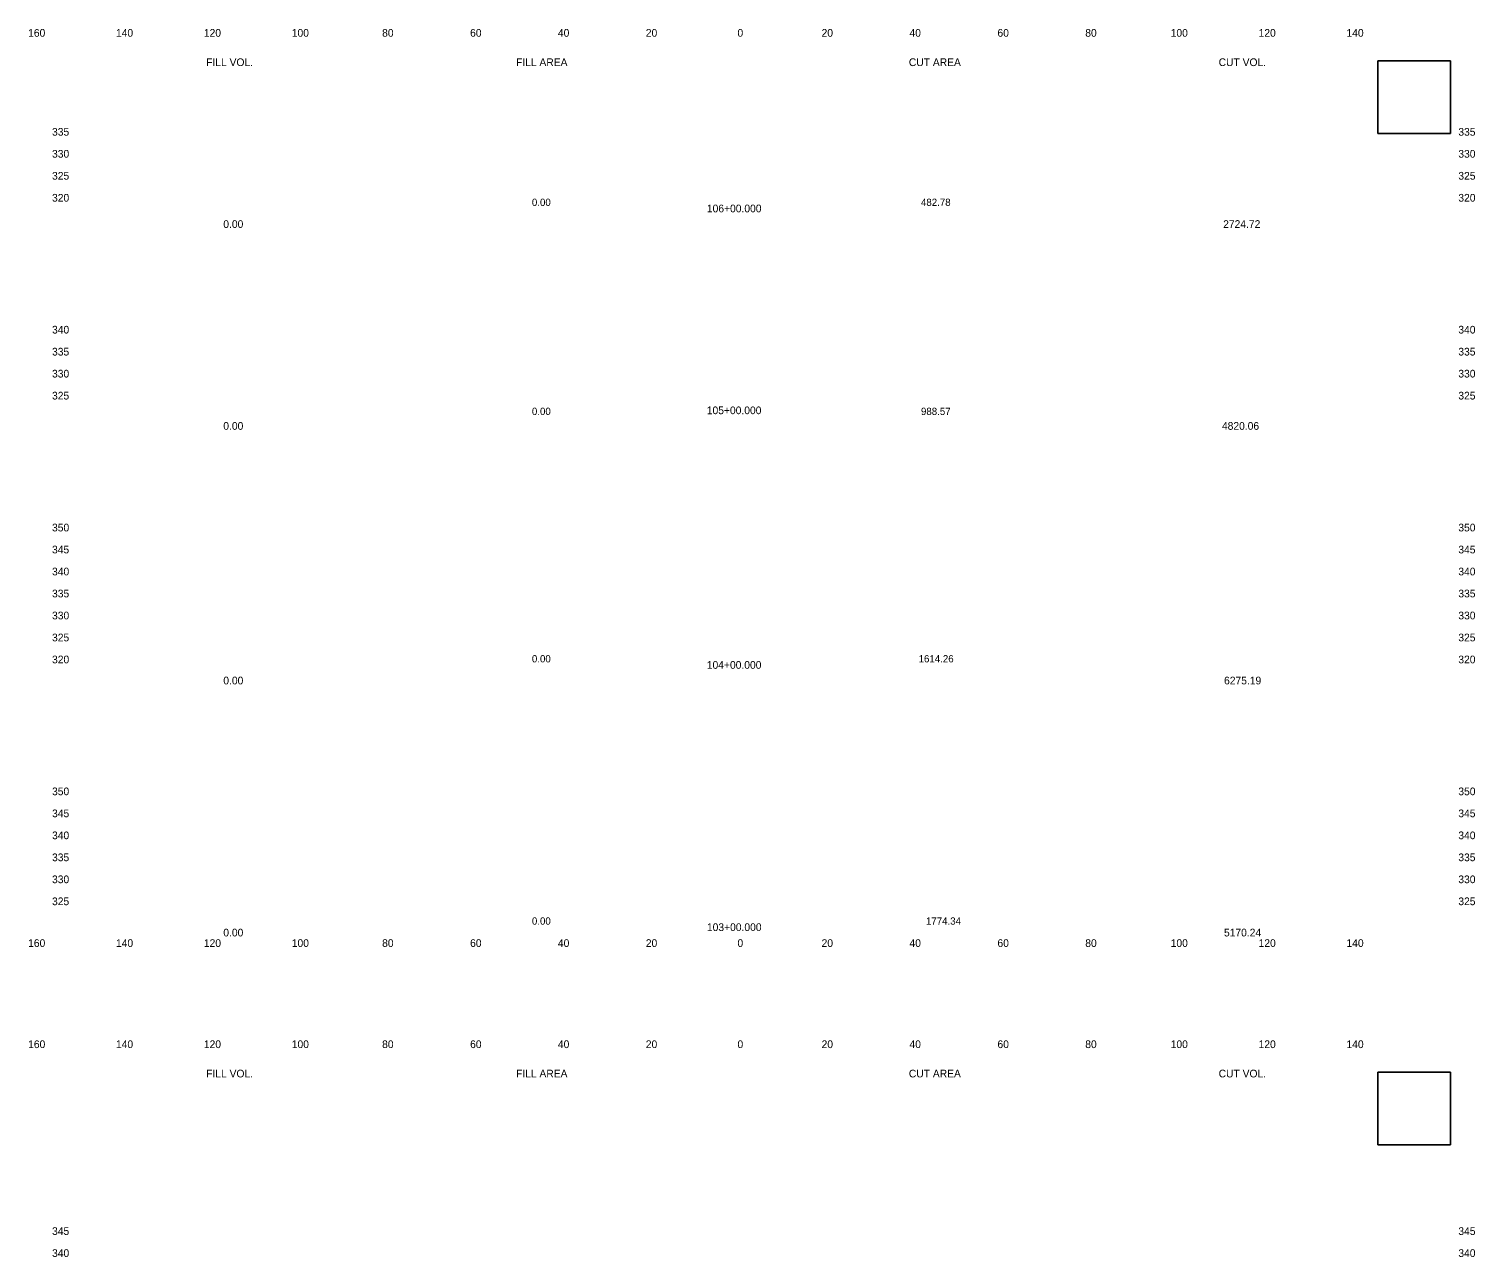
# Model space of a CAD drawing. Extents: x 21477 to 21806, y 6470 to 11049.
# Drawn here: x 21477.1 to 21806.1, y 7319.8 to 7599.1 of the extents above; entities that cross this region are included whole.
import ezdxf

# ---------------------------------------------------------------- set-up
doc = ezdxf.new("R2010")
doc.units = 0
for name, color, linetype in [('SHEET_CONSULTANT_STAMP', 7, 'Continuous'), ('XS_SHEET_EW_TX_AREA', 7, 'Continuous'), ('XS_SHEET_EW_TX_VOLUME', 7, 'Continuous'), ('XS_SHEET_LABELS_ELEVATION', 7, 'Continuous'), ('XS_SHEET_LABELS_OFFSET', 7, 'Continuous'), ('XS_SHEET_LABELS_STATION', 7, 'Continuous'), ('XS_SHEET_TX', 7, 'Continuous')]:
    doc.layers.add(name, color=color, linetype=linetype)

msp = doc.modelspace()

# ---------------------------------------------------------------- linework, layer by layer
at = {"layer": 'SHEET_CONSULTANT_STAMP'}
for points in [[(21784.04, 7575.34), (21800.54, 7575.34), (21800.54, 7591.84), (21784.04, 7591.84)], [(21784.04, 7345.34), (21800.54, 7345.34), (21800.54, 7361.84), (21784.04, 7361.84)]]:
    msp.add_lwpolyline(points, close=True, dxfattribs=at)

# ---------------------------------------------------------------- texts
at = {"layer": 'XS_SHEET_EW_TX_AREA'}
for s, p in [(' 0.00 ', (21590.92, 7558.86)), (' 482.78 ', (21679.45, 7558.86)), (' 0.00 ', (21590.92, 7511.32)), (' 988.57 ', (21679.45, 7511.32)), (' 0.00 ', (21590.92, 7455.05)), (' 1614.26 ', (21678.91, 7455.05)), (' 0.00 ', (21590.92, 7395.41)), (' 1774.34 ', (21680.58, 7395.41))]:
    msp.add_text(s, height=1.65, dxfattribs=at).set_placement(p)
at = {"layer": 'XS_SHEET_EW_TX_VOLUME'}
for s, p in [(' 0.00 ', (21520.66, 7553.86)), (' 2724.72 ', (21748.18, 7553.86)), (' 0.00 ', (21520.66, 7507.95)), (' 4820.06 ', (21747.9, 7507.95)), (' 0.00 ', (21520.66, 7450.05)), (' 6275.19 ', (21748.38, 7450.05)), (' 0.00 ', (21520.66, 7392.73)), (' 5170.24 ', (21748.36, 7392.73))]:
    msp.add_text(s, height=1.75, dxfattribs=at).set_placement(p)
at = {"layer": 'XS_SHEET_LABELS_ELEVATION'}
for s, p in [('  335  ', (21481.04, 7574.84)), ('  335  ', (21801.04, 7574.84)), ('  330  ', (21481.04, 7569.84)), ('  330  ', (21801.04, 7569.84)), ('  325  ', (21481.04, 7564.84)), ('  325  ', (21801.04, 7564.84)), ('  320  ', (21481.04, 7559.84)), ('  320  ', (21801.04, 7559.84)), ('  340  ', (21481.04, 7529.84)), ('  340  ', (21801.04, 7529.84)), ('  335  ', (21481.04, 7524.84)), ('  335  ', (21801.04, 7524.84)), ('  330  ', (21481.04, 7519.84)), ('  330  ', (21801.04, 7519.84)), ('  325  ', (21481.04, 7514.84)), ('  325  ', (21801.04, 7514.84)), ('  350  ', (21481.04, 7484.84)), ('  350  ', (21801.04, 7484.84)), ('  345  ', (21481.04, 7479.84)), ('  345  ', (21801.04, 7479.84)), ('  340  ', (21481.04, 7474.84)), ('  340  ', (21801.04, 7474.84)), ('  335  ', (21481.04, 7469.84)), ('  335  ', (21801.04, 7469.84)), ('  330  ', (21481.04, 7464.84)), ('  330  ', (21801.04, 7464.84)), ('  325  ', (21481.04, 7459.84)), ('  325  ', (21801.04, 7459.84)), ('  320  ', (21481.04, 7454.84)), ('  320  ', (21801.04, 7454.84)), ('  350  ', (21481.04, 7424.84)), ('  350  ', (21801.04, 7424.84)), ('  345  ', (21481.04, 7419.84)), ('  345  ', (21801.04, 7419.84)), ('  340  ', (21481.04, 7414.84)), ('  340  ', (21801.04, 7414.84)), ('  335  ', (21481.04, 7409.84)), ('  335  ', (21801.04, 7409.84)), ('  330  ', (21481.04, 7404.84)), ('  330  ', (21801.04, 7404.84)), ('  325  ', (21481.04, 7399.84)), ('  325  ', (21801.04, 7399.84)), ('  345  ', (21481.04, 7324.84)), ('  345  ', (21801.04, 7324.84)), ('  340  ', (21481.04, 7319.84)), ('  340  ', (21801.04, 7319.84))]:
    msp.add_text(s, height=1.75, dxfattribs=at).set_placement(p)
at = {"layer": 'XS_SHEET_LABELS_OFFSET'}
for s, p in [('  160  ', (21475.6, 7597.34)), ('  140  ', (21495.59, 7597.34)), ('  120  ', (21515.59, 7597.34)), ('  100  ', (21535.59, 7597.34)), ('  80  ', (21556.15, 7597.34)), ('  60  ', (21576.17, 7597.34)), ('  40  ', (21596.15, 7597.34)), ('  20  ', (21616.15, 7597.34)), ('  0  ', (21637.01, 7597.34)), ('  0  ', (21637.01, 7597.34)), ('  20  ', (21656.15, 7597.34)), ('  40  ', (21676.15, 7597.34)), ('  60  ', (21696.17, 7597.34)), ('  80  ', (21716.15, 7597.34)), ('  100  ', (21735.59, 7597.34)), ('  120  ', (21755.59, 7597.34)), ('  140  ', (21775.59, 7597.34)), ('  160  ', (21475.6, 7390.34)), ('  140  ', (21495.59, 7390.34)), ('  120  ', (21515.59, 7390.34)), ('  100  ', (21535.59, 7390.34)), ('  80  ', (21556.15, 7390.34)), ('  60  ', (21576.17, 7390.34)), ('  40  ', (21596.15, 7390.34)), ('  20  ', (21616.15, 7390.34)), ('  0  ', (21637.01, 7390.34)), ('  0  ', (21637.01, 7390.34)), ('  20  ', (21656.15, 7390.34)), ('  40  ', (21676.15, 7390.34)), ('  60  ', (21696.17, 7390.34)), ('  80  ', (21716.15, 7390.34)), ('  100  ', (21735.59, 7390.34)), ('  120  ', (21755.59, 7390.34)), ('  140  ', (21775.59, 7390.34)), ('  160  ', (21475.6, 7367.34)), ('  140  ', (21495.59, 7367.34)), ('  120  ', (21515.59, 7367.34)), ('  100  ', (21535.59, 7367.34)), ('  80  ', (21556.15, 7367.34)), ('  60  ', (21576.17, 7367.34)), ('  40  ', (21596.15, 7367.34)), ('  20  ', (21616.15, 7367.34)), ('  0  ', (21637.01, 7367.34)), ('  0  ', (21637.01, 7367.34)), ('  20  ', (21656.15, 7367.34)), ('  40  ', (21676.15, 7367.34)), ('  60  ', (21696.17, 7367.34)), ('  80  ', (21716.15, 7367.34)), ('  100  ', (21735.59, 7367.34)), ('  120  ', (21755.59, 7367.34)), ('  140  ', (21775.59, 7367.34))]:
    msp.add_text(s, height=1.75, dxfattribs=at).set_placement(p)
at = {"layer": 'XS_SHEET_LABELS_STATION'}
for s, p in [('  106+00.000  ', (21630.05, 7557.41)), ('  105+00.000  ', (21630.03, 7511.5)), ('  104+00.000  ', (21630.03, 7453.6)), ('  103+00.000  ', (21630.06, 7393.96))]:
    msp.add_text(s, height=1.75, dxfattribs=at).set_placement(p)
at = {"layer": 'XS_SHEET_TX'}
for s, p in [('FILL VOL.', (21517.41, 7590.67)), ('FILL AREA', (21587.92, 7590.67)), ('CUT AREA', (21677.31, 7590.67)), ('CUT VOL.', (21747.8, 7590.67)), ('FILL VOL.', (21517.41, 7360.67)), ('FILL AREA', (21587.92, 7360.67)), ('CUT AREA', (21677.31, 7360.67)), ('CUT VOL.', (21747.8, 7360.67))]:
    msp.add_text(s, height=1.75, dxfattribs=at).set_placement(p)

doc.saveas('drawing.dxf')
